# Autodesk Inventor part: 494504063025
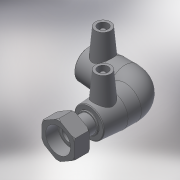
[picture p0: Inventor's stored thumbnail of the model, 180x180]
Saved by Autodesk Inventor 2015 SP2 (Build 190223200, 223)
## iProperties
Created: 2017-06
Part Number: 494504063025
Material: Generic
Description: PLASSON 90° ELBOW FEMALE FREE NUT TRANSITION 63-2.1/2"
Document SubType Name: Modeling
Designer: KIM
Mass: 55.0731 g
Surface Area: 148.067 cm^2
Volume: 55.0731 cm^3
Density: 1 g/cm^3
Appearance: Default
Author: KIM
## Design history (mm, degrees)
derived "494504.ipt"
feature "Solid1::494504.ipt"
tag "TaggingFeature1"
body "Solid1"
other parameters: "d2" = 82, "d4" = 43.66667, "d5" = 73.8, "d8" = 168 deg, "d10" = 22.8, "d11" = 7.6, "d29" = 59, "d30" = 15, "d31" = 72.05, "d34" = 5 deg, "d41" = 4, "d42" = 14, "d43" = 0, "d49" = 63, "d50" = 53.55, "d51" = 22.8, "d52" = 57, "d54" = 90 deg, "d57" = 63, "d58" = 57, "d59" = 0, "d61" = 90 deg, "d86" = 3, "d87" = 0, "d97" = 48, "d98" = 49, "d99" = 67.2675, "d109" = 1.89, "d116" = 24.5, "d117" = 44.845, "d118" = 19.6, "d119" = 1.96, "d120" = 35.876, "d121" = 1.96, "d122" = 31.3915, "d123" = 22.4225, "d124" = 2.24225, "d128" = 0, "d_" = 63, "L_1" = 57, "D_" = 48, "A_" = 59, "d_2" = 12, "L_2" = 49, "D_1" = 82, "G_" = 44.845
